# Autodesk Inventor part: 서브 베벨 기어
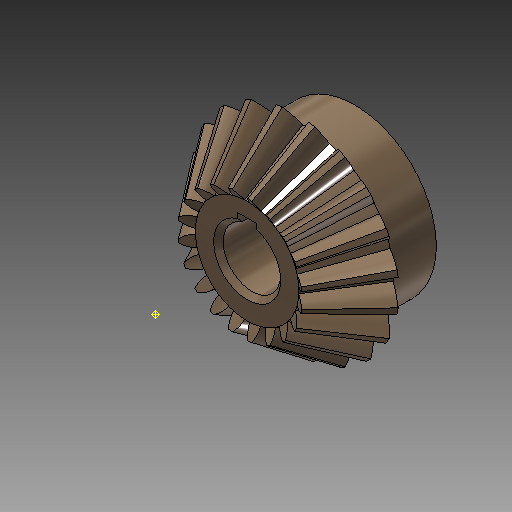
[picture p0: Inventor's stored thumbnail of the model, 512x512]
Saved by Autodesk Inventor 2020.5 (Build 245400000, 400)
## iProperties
CustomPartVersion: 1
Created: 2016-04
Part Number: 서브 베벨 기어
Material: 강철, 탄소
Document SubType Name: Modeling
Designer: mdu
Categories: <?xml version="1.0" encoding="UTF-16"?> <MemberInstance><Categories><FamilyTemplate><FamilyTemplateParameter ValueType="xs:double" Id="1" ObjectReferenceKey="da
Mass: 135.037 g
Surface Area: 63.6518 cm^2
Volume: 17.1585 cm^3
Density: 7.87 g/cm^3
Appearance: 얼룩무늬
Author: mdu
Revision Number: 1
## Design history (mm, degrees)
node "맨 위 점"
node "메쉬 평면2"
sketch "톱니 본체 스케치"
  geometry: L1 (0, 0)-(18.003, -31.331); L2 (18.003, -31.331)-(21.664, -28.891); L3 (21.664, -28.891)-(0, 0); L4 (20, -30)-(0, 0); L5 (10.813, -18.818)-(13.012, -17.352); L6 (18.003, -31.331)-(10.813, -18.818); L7 (21.664, -28.891)-(13.012, -17.352); L8 (0, -39.387)-(0, 6.564) reference; L9 (0, -30)-(21.664, -30)
  constraints: 16 end point, 4 point on line, 3 perpendicular, 2 collinear, 1 horizontal alignment, 1 vertical alignment
  dimensions: "d0" = 40 diameter of L4.start L8 (= da_de); "d1" = 36.00616 diameter of L1.end L8 (= da_dfe); "d2" = 43.3282 diameter of L2.end L8 (= da_dae); "d3" = 14.4 distance between parallel lines of L2 L5 (= da_b); "d4" = 28.8906 vertical distance of L2.end L1.start (= da_ve)
revolve "톱니 본체" sketch "톱니 본체 스케치" stored, may be unused: angle "d5" = 90 deg
node "시작점"
node "톱니 평면"
sketch "시작 스케치"
  geometry: L1 (0, -23.505)-(0, 10.645) reference; L2 (-0.834, -2.928)-(0.834, -2.928); A1 r 8.898 centre (-9.698, -3.713) between (-0.834, -2.928) and (-3.903, 3.04); A2 r 8.898 centre (9.698, -3.713) between (3.903, 3.04) and (0.834, -2.928); A3 r 27.357 centre (0, -24.037) between (3.903, 3.04) and (-3.903, 3.04); 1 further point
  constraints: 6 point on circle, 3 centre point, 3 symmetric about line, 2 end point, 1 coincident, 1 perpendicular, 1 other
  dimensions: "d7" = 8.89846 radius of A1 (= fd_rr); "d8" = 9.69794 horizontal distance of point (0, -24.037) A1.centre (= fd_x); "d9" = 20.32439 vertical distance of point (0, -24.037) A1.centre (= fd_y); "d57" = 27.35701 radius of A3 (= 0.5 x fd_dva + 0.3 x da_he); "d58" = 21.10901 distance from line of A3.centre L2 (= 0.5 x fd_dva - 1.12 x da_he)
node "끝점"
  node "끝 평면"
sketch "3D 스케치 오른쪽"
  node "Helical Curve Right" dims "d65" = 229.90621 (computed from da_dm, da_delta, da_beta), "d66" = 31.5, "d67" = 40 (= da_de), "d68" = -5.88003 (= -da_delta), "d69" = 12.16458 (computed from fd_loft, da_delta)
node "끝 평면 오른쪽"
sketch "끝 스케치 오른쪽"
  geometry: L1 (0, -22.649)-(0, 12.15) reference; L2 (-0.497, -1.72)-(0.497, -1.72); A1 r 5.299 centre (-5.775, -2.187) between (-0.497, -1.72) and (-2.324, 1.834); A2 r 5.299 centre (5.775, -2.187) between (2.324, 1.834) and (0.497, -1.72); A3 r 16.291 centre (0, -14.29) between (2.324, 1.834) and (-2.324, 1.834); 1 further point
  constraints: 6 point on circle, 3 centre point, 3 symmetric about line, 2 end point, 1 coincident, 1 perpendicular, 1 other
  dimensions: "d70" = 5.77526 horizontal distance of A3.centre A1.centre (computed from fd_x, fd_ratio); "d71" = 12.10346 vertical distance of point (0, -14.29) A1.centre (computed from fd_y, fd_ratio); "d72" = 5.29916 radius of A1 (computed from fd_rr, fd_ratio); "d73" = 12.57071 distance from line of point (0, -14.29) L2 (computed from d58, fd_ratio); "d74" = 16.29149 radius of A3 (computed from d57, fd_ratio)
feature "로프트 오른쪽" sketch "끝 스케치 오른쪽" dims "d75" = 0, "d77" = 0, "d79" = 0, "d80" = 90 deg, "d85" = 20, "d92" = 90 deg, "d93" = 90 deg, "da_teethtype" = 0 [user parameter]
sketch "3D 스케치 왼쪽"
  node "Helical Curve Left" dims "d26" = 229.90621 (computed from da_dm, da_delta, da_beta), "d27" = 12.16458 (computed from fd_loft, da_delta), "d28" = 40 (= da_de), "d29" = -5.88003 (= -da_delta)
node "끝 평면 왼쪽"
sketch "끝 스케치 왼쪽" dims "d56" = 10.82768 (derived)
  geometry: L1 (0, -35.087)-(0, 18.089) reference; L2 (-0.497, -1.716)-(0.497, -1.716); A1 r 5.299 centre (-5.775, -2.183) between (-0.497, -1.716) and (-2.324, 1.838); A2 r 5.299 centre (5.775, -2.183) between (2.324, 1.838) and (0.497, -1.716); A3 r 16.291 centre (0, -14.287) between (2.324, 1.838) and (-2.324, 1.838); 2 further points; 1 other entity
  constraints: 6 point on circle, 3 centre point, 3 symmetric about line, 2 end point, 1 coincident, 2 other
  dimensions: "d30" = 5.29916 radius of A1 (computed from fd_rr, fd_ratio); "d31" = 5.77526 horizontal distance of point (0, -14.287) A1.centre (computed from fd_x, fd_ratio); "d32" = 12.10346 vertical distance of A1.centre point (0, -14.287) (computed from fd_y, fd_ratio); "d61" = 16.29149 radius of A3 (computed from d57, fd_ratio); "d62" = 12.57071 distance from line of point (0, -14.287) L2 (computed from d58, fd_ratio)
feature "로프트 왼쪽" sketch "끝 스케치 왼쪽" dims "d35" = 0, "d37" = 0, "d39" = 0, "d40" = 90 deg, "d84" = 10, "d90" = 90 deg, "d91" = 90 deg, "da_teethtype" = 0 [user parameter]
sketch "본체 스케치"
  geometry: L1 (0, -35.038)-(0, -19.531) reference; L2 (18.003, -31.331)-(10.813, -18.818) reference; L3 (10.813, -18.818)-(0, -18.818); L4 (18.003, -31.331)-(0, -31.331)
  constraints: 4 end point, 2 perpendicular, 2 point on line
revolve "본체 고정" sketch "본체 스케치" stored, may be unused: angle "d46" = 90 deg
feature "피치 지름" dims angle "d47" = 90 deg
sketch "스케치8"
  geometry: C1 r 17 at (0, 0); 1 further point
  constraints: 1 centre point, 1 coincident
  dimensions: "d94" = 34 diameter of C1
extrude "돌출1" join sketch "스케치8" distance "d95" = 10; taper "d96" = 0 deg
sketch "스케치9"
  geometry: 1 further point
hole "구멍1" sketch "스케치9" at (0, 0) diameter "d97" = 12; stored, may be unused: countersink angle "d101" = 90 deg, drill point angle "d103" = 118 deg; dims "d98" = 6, "d99" = 4, "d100" = 2, "d102" = 8
sketch "스케치10"
  geometry: 1 further point
sketch "스케치11"
  geometry: 1 further point
sketch "스케치12"
  geometry: L1 (-2, 5.657)-(-2, 7.8); L2 (-2, 7.8)-(2, 7.8); L3 (2, 7.8)-(2, 5.657); A1 r 6 centre (0, 0) between (-2, 5.657) and (2, 5.657) reference; 1 further point
  constraints: 6 end point, 2 parallel, 2 point on circle, 1 perpendicular, 1 vertical
  dimensions: "d104" = 4 distance of L1.end L2.end; "d105" = 13.8 dimension on A1 L2
extrude "돌출2" cut sketch "스케치12" extent not by distance; stored distance "d106" = 7; taper "d107" = 0 deg
chamfer "모따기1" distance "d108" = 1; stored, may be unused: second distance "d109" = 2, angle "d110" = 45 deg
body "Solid1"
feature "로프트" dims "d17" = 0, "d18" = 90 deg, "d19" = 0, "d20" = 90 deg, "d89" = 0, "da_teethtype" = 0 [user parameter]
pattern_circular "원형 패턴" dims angle "d22" = 360 deg, "d88" = 0, "da_teethtype" = 0 [user parameter]
pattern_circular "원형 패턴 오른쪽" dims angle "d82" = 360 deg, "da_teethtype" = 0 [user parameter]
pattern_circular "원형 패턴 왼쪽" dims angle "d42" = 360 deg, "da_teethtype" = 0 [user parameter]
sketch "끝 스케치"
  geometry: L1 (0, -15.359)-(0, 6.983) reference; L2 (-0.497, -1.72)-(0.497, -1.72); A1 r 5.299 centre (-5.775, -2.187) between (-0.497, -1.72) and (-2.324, 1.834); A2 r 5.299 centre (5.775, -2.187) between (2.324, 1.834) and (0.497, -1.72); A3 r 16.291 centre (0, -14.29) between (2.324, 1.834) and (-2.324, 1.834); 1 further point
  constraints: 6 point on circle, 3 centre point, 3 symmetric about line, 2 end point, 1 coincident, 1 other
  dimensions: "d12" = 5.29916 radius of A1 (computed from fd_rr, fd_ratio); "d15" = 5.77526 horizontal distance of A1.centre point (0, -14.29) (computed from fd_x, fd_ratio); "d16" = 12.10346 vertical distance of A1.centre point (0, -14.29) (computed from fd_y, fd_ratio); "d59" = 16.29149 radius of A3 (computed from d57, fd_ratio); "d60" = 12.57071 distance from line of A3.centre L2 (computed from d58, fd_ratio)
sketch "Sketch6"
  geometry: L1 (20, -30)-(0, 0) reference; L2 (0, -37.8)-(0, 6.3) reference
body "Srf1"
other parameters: "da_b" = 14.4 [user parameter; used in 2 equation terms], "da_de" = 40 [user parameter; used in 4 equation terms], "da_dae" = 43.3282 [user parameter; used in 2 equation terms], "da_dfe" = 36.00616 [user parameter; used in 1 equation term], "da_le" = 36.05551 [user parameter; used in 1 equation term], "da_omega" = 90 deg [user parameter; used in 1 equation term], "da_beta" = 0 [user parameter; used in 2 equation terms], "da_delta" = 5.88003 [user parameter; used in 8 equation terms], "da_alpha" = 20 deg [user parameter; used in 2 equation terms], "da_he" = 4.4 [user parameter; used in 4 equation terms], "da_ve" = 28.8906 [user parameter; used in 1 equation term], "fd_dv" = 48.07402 (computed from da_de, da_delta) [user parameter; used in 1 equation term], "fd_dva" = 52.07402 (computed from da_dae, da_delta) [user parameter; used in 3 equation terms], "fd_dvb" = 45.1748 (computed from fd_dv, da_alpha) [user parameter; used in 2 equation terms], "da_zv" = 240.37008 [user parameter; used in 1 equation term], "fd_loft" = 14.62 (= da_b + 0.05 x da_he) [user parameter; used in 4 equation terms], "fd_ratio" = 5.95514 (computed from da_le, fd_loft) [user parameter; used in 15 equation terms], "fd_rr" = 8.89846 (computed from fd_dd, fd_dvb) [user parameter; used in 6 equation terms], "fd_angle" = 0.66075 (computed from da_zv) [user parameter; used in 4 equation terms], "fd_x1" = 1.58709 (computed from da_dvw, fd_angle) [user parameter; used in 1 equation term], "fd_y1" = 23.98456 (computed from da_dvw, fd_angle) [user parameter; used in 1 equation term], "fd_x2" = 8.11084 (computed from fd_rr, fd_angle2, fd_angle) [user parameter; used in 1 equation term], "fd_y2" = 3.66016 (computed from fd_rr, fd_angle2, fd_angle) [user parameter; used in 1 equation term], "fd_x" = 9.69794 (= fd_x1 + fd_x2) [user parameter; used in 4 equation terms], "fd_y" = 20.32439 (= fd_y1 - fd_y2) [user parameter; used in 4 equation terms], "fd_angle2" = 3.57832 (computed from fd_dvb, fd_dd, da_alpha) [user parameter; used in 2 equation terms], "fd_dd" = 48.55402 (= fd_dva - 0.8 x da_he) [user parameter; used in 2 equation terms], "da_dvw" = 48.07402 [user parameter; used in 2 equation terms], "d11" = 14.62 (= fd_loft), "da_dm" = 32.01232 [user parameter; used in 2 equation terms], "da_x" = 0 [user parameter], "da_m" = 2 [user parameter], "d48" = 0, "d49" = 0, "d50" = 90 deg (= da_omega), "d51" = 9 deg (computed from da_z), "d52" = 0, "d53" = 0, "d54" = 0
